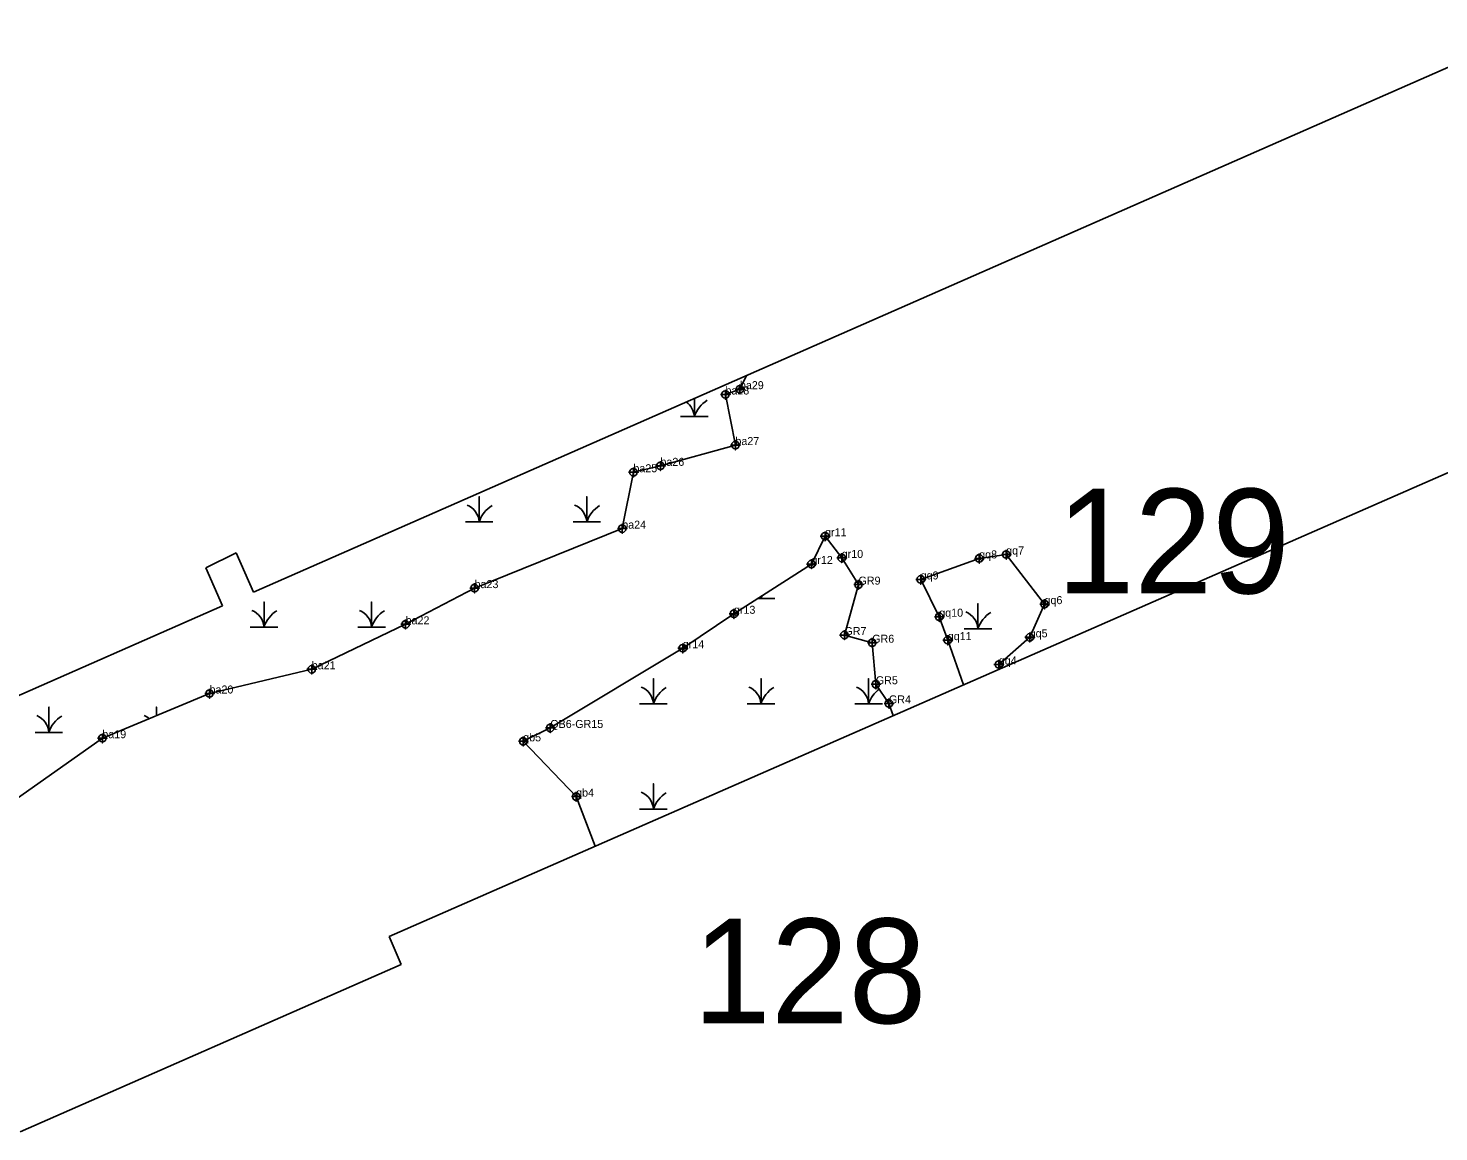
# Model space of a CAD drawing. Extents: x 2071991 to 2268989, y 436479 to 469629.
# Drawn here: x 2154267 to 2155148, y 438792 to 439481 of the extents above; entities that cross this region are included whole.
import ezdxf

# ---------------------------------------------------------------- set-up
doc = ezdxf.new("R2010")
doc.units = 0
for name, color, linetype in [('approx_PSA', 7, 'Continuous'), ('Default', 7, 'Continuous'), ('Exist Environmental Wetland Boundary', 7, 'Continuous'), ('Exist Environmental Wetland Boundary Cogo Comment', 7, 'Continuous'), ('Exist Environmental Wetland Boundary Cogo Point CELL', 7, 'Continuous'), ('Exist Hydro Swamp or Marsh', 7, 'Continuous')]:
    doc.layers.add(name, color=color, linetype=linetype)

msp = doc.modelspace()

# ---------------------------------------------------------------- linework, layer by layer
at = {"layer": 'approx_PSA'}
for p, q in [((2154984.35, 439382.15), (2155209.56, 439481.14)), ((2154407.61, 439128.65), (2154984.35, 439382.15)), ((2155471.95, 439342.96), (2154492.32, 438913.55)), ((2154377.92, 439144), (2154396.74, 439153.36)), ((2154396.74, 439153.36), (2154407.61, 439128.65)), ((2154388.38, 439120.2), (2154377.92, 439144)), ((2153770.44, 438848.59), (2154388.38, 439120.2)), ((2154492.32, 438913.55), (2154499.96, 438896.16)), ((2154499.96, 438896.16), (2154261.94, 438791.54))]:
    msp.add_line(p, q, dxfattribs=at)
at = {"layer": 'Exist Environmental Wetland Boundary'}
for points in [[(2154248.07, 438991.39), (2154313.26, 439037.49), (2154380.2, 439065.41), (2154444.06, 439080.52), (2154502.7, 439108.64), (2154545.78, 439131.27), (2154638.01, 439168.43), (2154644.99, 439203.68), (2154661.86, 439207.67), (2154708.7, 439220.64), (2154702.47, 439252.26), (2154711.52, 439255.58), (2154715.72, 439264.07)], [(2154621.12, 438970.01), (2154609.21, 439000.98), (2154576.13, 439035.53), (2154593.05, 439043.88), (2154675.82, 439093.72), (2154707.77, 439115.23), (2154756.14, 439146.32), (2154764.72, 439163.72), (2154775.11, 439150.13), (2154785.59, 439133.45), (2154776.79, 439101.96), (2154794.14, 439097.14), (2154796.42, 439071.19), (2154804.6, 439059.22), (2154807.27, 439051.61)], [(2154874, 439080.85), (2154873.22, 439083.54), (2154892.52, 439100.52), (2154901.79, 439121.27), (2154877.83, 439152.27), (2154861, 439149.82), (2154824.44, 439136.7), (2154836.04, 439113.4), (2154841.35, 439098.78), (2154851.2, 439070.86)]]:
    msp.add_lwpolyline(points, dxfattribs=at)
at = {"layer": 'Exist Environmental Wetland Boundary Cogo Point CELL'}
for points in [[(2154702.47, 439255.26), (2154702.47, 439249.26), (2154702.47, 439252.26), (2154705.47, 439252.26), (2154699.47, 439252.26)], [(2154711.52, 439258.58), (2154711.52, 439252.58), (2154711.52, 439255.58), (2154714.52, 439255.58), (2154708.52, 439255.58)], [(2154708.7, 439223.64), (2154708.7, 439217.64), (2154708.7, 439220.64), (2154711.7, 439220.64), (2154705.7, 439220.64)], [(2154661.86, 439210.67), (2154661.86, 439204.67), (2154661.86, 439207.67), (2154664.86, 439207.67), (2154658.86, 439207.67)], [(2154644.99, 439206.68), (2154644.99, 439200.68), (2154644.99, 439203.68), (2154647.99, 439203.68), (2154641.99, 439203.68)], [(2154638.01, 439171.43), (2154638.01, 439165.43), (2154638.01, 439168.43), (2154641.01, 439168.43), (2154635.01, 439168.43)], [(2154764.72, 439166.72), (2154764.72, 439160.72), (2154764.72, 439163.72), (2154767.72, 439163.72), (2154761.72, 439163.72)], [(2154877.83, 439155.27), (2154877.83, 439149.27), (2154877.83, 439152.27), (2154880.83, 439152.27), (2154874.83, 439152.27)], [(2154756.14, 439149.32), (2154756.14, 439143.32), (2154756.14, 439146.32), (2154759.14, 439146.32), (2154753.14, 439146.32)], [(2154775.11, 439153.13), (2154775.11, 439147.13), (2154775.11, 439150.13), (2154778.11, 439150.13), (2154772.11, 439150.13)], [(2154861, 439152.82), (2154861, 439146.82), (2154861, 439149.82), (2154864, 439149.82), (2154858, 439149.82)], [(2154824.44, 439139.7), (2154824.44, 439133.7), (2154824.44, 439136.7), (2154827.44, 439136.7), (2154821.44, 439136.7)], [(2154545.78, 439134.27), (2154545.78, 439128.27), (2154545.78, 439131.27), (2154548.78, 439131.27), (2154542.78, 439131.27)], [(2154785.59, 439136.45), (2154785.59, 439130.45), (2154785.59, 439133.45), (2154788.59, 439133.45), (2154782.59, 439133.45)], [(2154901.79, 439124.27), (2154901.79, 439118.27), (2154901.79, 439121.27), (2154904.79, 439121.27), (2154898.79, 439121.27)], [(2154502.7, 439111.64), (2154502.7, 439105.64), (2154502.7, 439108.64), (2154505.7, 439108.64), (2154499.7, 439108.64)], [(2154707.77, 439118.23), (2154707.77, 439112.23), (2154707.77, 439115.23), (2154710.77, 439115.23), (2154704.77, 439115.23)], [(2154836.04, 439116.4), (2154836.04, 439110.4), (2154836.04, 439113.4), (2154839.04, 439113.4), (2154833.04, 439113.4)], [(2154776.79, 439104.96), (2154776.79, 439098.96), (2154776.79, 439101.96), (2154779.79, 439101.96), (2154773.79, 439101.96)], [(2154892.52, 439103.52), (2154892.52, 439097.52), (2154892.52, 439100.52), (2154895.52, 439100.52), (2154889.52, 439100.52)], [(2154675.82, 439096.72), (2154675.82, 439090.72), (2154675.82, 439093.72), (2154678.82, 439093.72), (2154672.82, 439093.72)], [(2154794.14, 439100.14), (2154794.14, 439094.14), (2154794.14, 439097.14), (2154797.14, 439097.14), (2154791.14, 439097.14)], [(2154841.35, 439101.78), (2154841.35, 439095.78), (2154841.35, 439098.78), (2154844.35, 439098.78), (2154838.35, 439098.78)], [(2154873.22, 439086.54), (2154873.22, 439080.54), (2154873.22, 439083.54), (2154876.22, 439083.54), (2154870.22, 439083.54)], [(2154444.06, 439083.52), (2154444.06, 439077.52), (2154444.06, 439080.52), (2154447.06, 439080.52), (2154441.06, 439080.52)], [(2154380.2, 439068.41), (2154380.2, 439062.41), (2154380.2, 439065.41), (2154383.2, 439065.41), (2154377.2, 439065.41)], [(2154796.42, 439074.19), (2154796.42, 439068.19), (2154796.42, 439071.19), (2154799.42, 439071.19), (2154793.42, 439071.19)], [(2154804.6, 439062.22), (2154804.6, 439056.22), (2154804.6, 439059.22), (2154807.6, 439059.22), (2154801.6, 439059.22)], [(2154313.26, 439040.49), (2154313.26, 439034.49), (2154313.26, 439037.49), (2154316.26, 439037.49), (2154310.26, 439037.49)], [(2154593.05, 439046.88), (2154593.05, 439040.88), (2154593.05, 439043.88), (2154596.05, 439043.88), (2154590.05, 439043.88)], [(2154576.13, 439038.53), (2154576.13, 439032.53), (2154576.13, 439035.53), (2154579.13, 439035.53), (2154573.13, 439035.53)], [(2154609.21, 439003.98), (2154609.21, 438997.98), (2154609.21, 439000.98), (2154612.21, 439000.98), (2154606.21, 439000.98)]]:
    msp.add_lwpolyline(points, dxfattribs=at)
for centre in [(2154702.47, 439252.26), (2154711.52, 439255.58), (2154708.7, 439220.64), (2154661.86, 439207.67), (2154644.99, 439203.68), (2154638.01, 439168.43), (2154764.72, 439163.72), (2154756.14, 439146.32), (2154775.11, 439150.13), (2154861, 439149.82), (2154877.83, 439152.27), (2154824.44, 439136.7), (2154545.78, 439131.27), (2154785.59, 439133.45), (2154901.79, 439121.27), (2154502.7, 439108.64), (2154707.77, 439115.23), (2154836.04, 439113.4), (2154776.79, 439101.96), (2154892.52, 439100.52), (2154675.82, 439093.72), (2154794.14, 439097.14), (2154841.35, 439098.78), (2154873.22, 439083.54), (2154444.06, 439080.52), (2154380.2, 439065.41), (2154796.42, 439071.19), (2154804.6, 439059.22), (2154593.05, 439043.88), (2154313.26, 439037.49), (2154576.13, 439035.53), (2154609.21, 439000.98)]:
    msp.add_circle(centre, 2.34, dxfattribs=at)
at = {"layer": 'Exist Hydro Swamp or Marsh'}
for points in [[(2154674.45, 439238.46), (2154683.05, 439238.46), (2154683.05, 439249.72)], [(2154683.05, 439249.72), (2154683.05, 439238.46), (2154691.65, 439238.46)], [(2154540.04, 439172.68), (2154548.65, 439172.68), (2154548.65, 439188.46), (2154548.65, 439172.68), (2154557.25, 439172.68)], [(2154607.25, 439172.68), (2154615.85, 439172.68), (2154615.85, 439188.46), (2154615.85, 439172.68), (2154624.45, 439172.68)], [(2154405.64, 439106.9), (2154414.24, 439106.9), (2154414.24, 439122.68), (2154414.24, 439106.9), (2154422.84, 439106.9)], [(2154472.84, 439106.9), (2154481.44, 439106.9), (2154481.44, 439122.68), (2154481.44, 439106.9), (2154490.04, 439106.9)], [(2154722.58, 439124.75), (2154724.68, 439124.75), (2154724.68, 439126.1)], [(2154724.68, 439126.1), (2154724.68, 439124.75), (2154733.28, 439124.75)], [(2154851.62, 439105.87), (2154860.22, 439105.87), (2154860.22, 439121.65), (2154860.22, 439105.87), (2154868.82, 439105.87)], [(2154648.87, 439058.97), (2154657.47, 439058.97), (2154657.47, 439074.75), (2154657.47, 439058.97), (2154666.08, 439058.97)], [(2154716.08, 439058.97), (2154724.68, 439058.97), (2154724.68, 439074.75), (2154724.68, 439058.97), (2154733.28, 439058.97)], [(2154783.28, 439058.97), (2154791.88, 439058.97), (2154791.88, 439074.75), (2154791.88, 439058.97), (2154800.48, 439058.97)], [(2154271.23, 439041.12), (2154279.83, 439041.12), (2154279.83, 439056.9), (2154279.83, 439041.12), (2154288.44, 439041.12)], [(2154347.04, 439051.58), (2154347.04, 439056.9), (2154347.04, 439051.58)], [(2154648.87, 438993.19), (2154657.47, 438993.19), (2154657.47, 439008.97), (2154657.47, 438993.19), (2154666.08, 438993.19)]]:
    msp.add_lwpolyline(points, dxfattribs=at)
for centre, radius, start, end in [((2154670.79, 439237.58), 12.3, 4.14034, 53.88282), ((2154701.3, 439232.4), 19.22, 122.12745, 161.62219), ((2154536.38, 439171.8), 12.3, 4.14034, 67.53497), ((2154566.89, 439166.62), 19.22, 122.12745, 161.62219), ((2154603.58, 439171.8), 12.3, 4.14034, 67.53497), ((2154634.09, 439166.62), 19.22, 122.12745, 161.62219), ((2154779.61, 439123.86), 12.3, 66.4224, 67.53497), ((2154712.41, 439123.86), 12.3, 4.14034, 9.99286), ((2154742.92, 439118.69), 19.22, 155.88355, 161.62219), ((2154401.97, 439106.01), 12.3, 4.14034, 67.53497), ((2154432.48, 439100.84), 19.22, 122.12745, 161.62219), ((2154469.18, 439106.01), 12.3, 4.14034, 67.53497), ((2154499.69, 439100.84), 19.22, 122.12745, 161.62219), ((2154847.95, 439104.98), 12.3, 4.14034, 67.53497), ((2154878.46, 439099.81), 19.22, 122.12745, 161.62219), ((2154645.21, 439058.08), 12.3, 4.14034, 67.53497), ((2154675.72, 439052.91), 19.22, 122.12745, 161.62219), ((2154712.41, 439058.08), 12.3, 4.14034, 67.53497), ((2154742.92, 439052.91), 19.22, 122.12745, 161.62219), ((2154779.61, 439058.08), 12.3, 4.14034, 67.53497), ((2154810.12, 439052.91), 19.22, 127.32324, 161.62219), ((2154267.57, 439040.23), 12.3, 4.14034, 67.53497), ((2154298.08, 439035.06), 19.22, 122.12745, 161.62219), ((2154334.77, 439040.23), 12.3, 50.49822, 67.53497), ((2154645.21, 438992.3), 12.3, 4.14034, 67.53497), ((2154675.72, 438987.13), 19.22, 122.12745, 161.62219)]:
    msp.add_arc(centre, radius, start, end, dxfattribs=at)

# ---------------------------------------------------------------- texts
at = {"layer": 'Default'}
for s, p in [('129', (2154909.35, 439127.97)), ('128', (2154682.23, 438859.41))]:
    msp.add_text(s, height=65.34, dxfattribs=at).set_placement(p)
at = {"layer": 'Exist Environmental Wetland Boundary Cogo Comment'}
for s, p in [('ba29', (2154711.52, 439255.58)), ('ba28', (2154702.47, 439252.26)), ('ba27', (2154708.7, 439220.64)), ('ba25', (2154644.99, 439203.68)), ('ba26', (2154661.86, 439207.67)), ('ba24', (2154638.01, 439168.43)), ('gr11', (2154764.72, 439163.72)), ('gr10', (2154775.11, 439150.13)), ('gq8', (2154861, 439149.82)), ('gq7', (2154877.83, 439152.27)), ('gr12', (2154756.14, 439146.32)), ('GR9', (2154785.59, 439133.45)), ('gq9', (2154824.44, 439136.7)), ('ba23', (2154545.78, 439131.27)), ('gr13', (2154707.77, 439115.23)), ('gq6', (2154901.79, 439121.27)), ('ba22', (2154502.7, 439108.64)), ('gq10', (2154836.04, 439113.4)), ('GR7', (2154776.79, 439101.96)), ('GR6', (2154794.14, 439097.14)), ('gq11', (2154841.35, 439098.78)), ('gq5', (2154892.52, 439100.52)), ('gr14', (2154675.82, 439093.72)), ('ba21', (2154444.06, 439080.52)), ('gq4', (2154873.22, 439083.54)), ('GR5', (2154796.42, 439071.19)), ('ba20', (2154380.2, 439065.41)), ('GR4', (2154804.6, 439059.22)), ('ba19', (2154313.26, 439037.49)), ('qb5', (2154576.13, 439035.53)), ('QB6-GR15', (2154593.05, 439043.88)), ('qb4', (2154609.21, 439000.98))]:
    msp.add_text(s, height=5, dxfattribs=at).set_placement(p)

doc.saveas('drawing.dxf')
